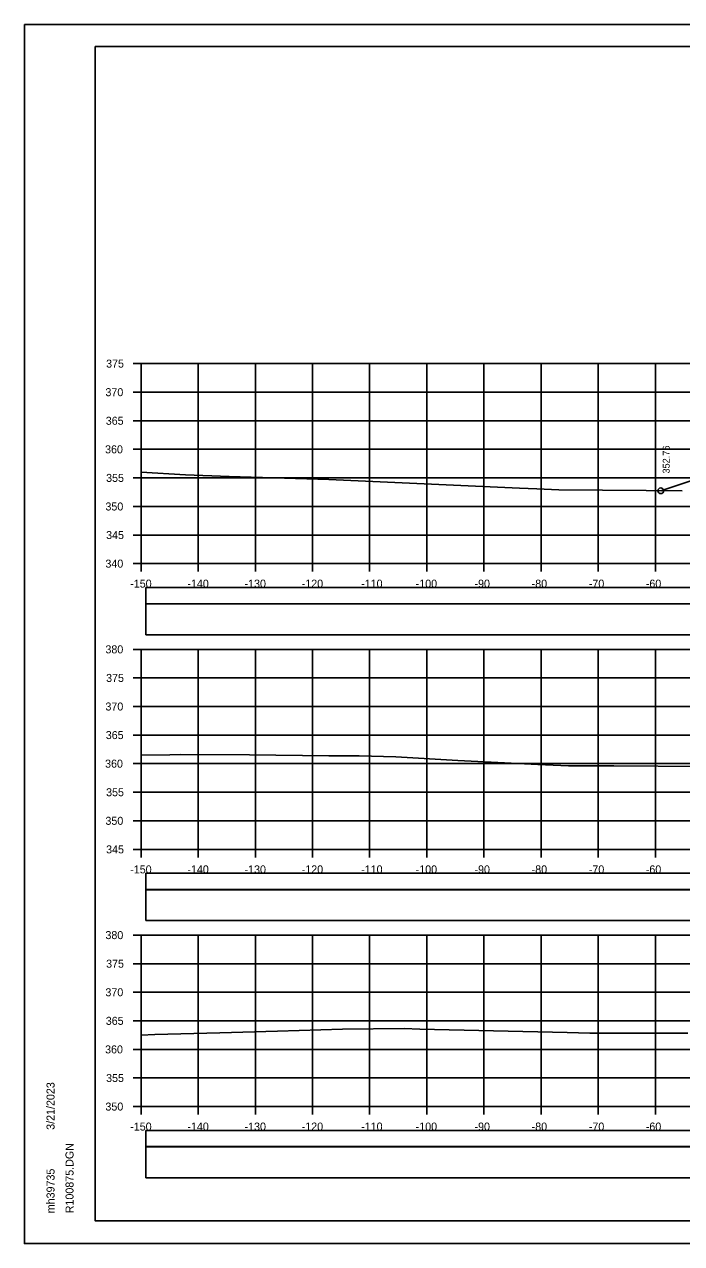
# Model space of a CAD drawing. Extents: x 1368122 to 1710785, y 373130 to 557566.
# Drawn here: x 1368518.5 to 1368633.5, y 376117.1 to 376330.4 of the extents above; entities that cross this region are included whole.
import ezdxf

# ---------------------------------------------------------------- set-up
doc = ezdxf.new("R2010")
doc.units = 0
for name, color, linetype in [('R_Alt Surface', 7, 'Continuous'), ('R_Axis', 7, 'Continuous'), ('R_Axis Annot', 7, 'Continuous'), ('R_Border', 7, 'Continuous'), ('R_Exist Surface', 7, 'Continuous'), ('R_Fin Surface', 7, 'Continuous'), ('R_Grid', 7, 'Continuous'), ('R_No Plot', 7, 'Continuous'), ('R_Xsect Elev', 7, 'Continuous')]:
    doc.layers.add(name, color=color, linetype=linetype)

msp = doc.modelspace()

# ---------------------------------------------------------------- linework, layer by layer
for points in [[(1368539.73, 376223.57), (1368838.03, 376223.57), (1368838.03, 376228.98), (1368539.73, 376228.98)], [(1368539.73, 376173.57), (1368838.03, 376173.57), (1368838.03, 376178.98), (1368539.73, 376178.98)], [(1368539.73, 376128.57), (1368838.03, 376128.57), (1368838.03, 376133.98), (1368539.73, 376133.98)]]:
    msp.add_lwpolyline(points, close=True)
at = {"layer": 'R_Alt Surface'}
for points in [[(1368539.73, 376229.03), (1368838.03, 376229.03), (1368838.03, 376231.85), (1368539.73, 376231.85)], [(1368539.73, 376179.03), (1368838.03, 376179.03), (1368838.03, 376181.85), (1368539.73, 376181.85)], [(1368539.73, 376134.03), (1368838.03, 376134.03), (1368838.03, 376136.85), (1368539.73, 376136.85)]]:
    msp.add_lwpolyline(points, close=True, dxfattribs=at)
at = {"layer": 'R_Axis'}
for p, q in [((1368537.48, 376271.04), (1368538.88, 376271.04)), ((1368538.88, 376236.04), (1368538.88, 376271.04)), ((1368537.48, 376266.04), (1368538.88, 376266.04)), ((1368537.48, 376261.04), (1368538.88, 376261.04)), ((1368537.48, 376256.04), (1368538.88, 376256.04)), ((1368537.48, 376251.04), (1368538.88, 376251.04)), ((1368537.48, 376246.04), (1368538.88, 376246.04)), ((1368537.48, 376241.04), (1368538.88, 376241.04)), ((1368537.48, 376236.04), (1368538.88, 376236.04)), ((1368538.88, 376236.04), (1368838.88, 376236.04)), ((1368538.88, 376234.64), (1368538.88, 376236.04)), ((1368548.88, 376234.64), (1368548.88, 376236.04)), ((1368558.88, 376234.64), (1368558.88, 376236.04)), ((1368568.88, 376234.64), (1368568.88, 376236.04)), ((1368578.88, 376234.64), (1368578.88, 376236.04)), ((1368588.88, 376234.64), (1368588.88, 376236.04)), ((1368598.88, 376234.64), (1368598.88, 376236.04)), ((1368608.88, 376234.64), (1368608.88, 376236.04)), ((1368618.88, 376234.64), (1368618.88, 376236.04)), ((1368628.88, 376234.64), (1368628.88, 376236.04)), ((1368537.48, 376221.04), (1368538.88, 376221.04)), ((1368538.88, 376186.04), (1368538.88, 376221.04)), ((1368537.48, 376216.04), (1368538.88, 376216.04)), ((1368537.48, 376211.04), (1368538.88, 376211.04)), ((1368537.48, 376206.04), (1368538.88, 376206.04)), ((1368537.48, 376201.04), (1368538.88, 376201.04)), ((1368537.48, 376196.04), (1368538.88, 376196.04)), ((1368537.48, 376191.04), (1368538.88, 376191.04)), ((1368537.48, 376186.04), (1368538.88, 376186.04)), ((1368538.88, 376186.04), (1368838.88, 376186.04)), ((1368538.88, 376184.64), (1368538.88, 376186.04)), ((1368548.88, 376184.64), (1368548.88, 376186.04)), ((1368558.88, 376184.64), (1368558.88, 376186.04)), ((1368568.88, 376184.64), (1368568.88, 376186.04)), ((1368578.88, 376184.64), (1368578.88, 376186.04)), ((1368588.88, 376184.64), (1368588.88, 376186.04)), ((1368598.88, 376184.64), (1368598.88, 376186.04)), ((1368608.88, 376184.64), (1368608.88, 376186.04)), ((1368618.88, 376184.64), (1368618.88, 376186.04)), ((1368628.88, 376184.64), (1368628.88, 376186.04)), ((1368537.48, 376171.04), (1368538.88, 376171.04)), ((1368538.88, 376141.04), (1368538.88, 376171.04)), ((1368537.48, 376166.04), (1368538.88, 376166.04)), ((1368537.48, 376161.04), (1368538.88, 376161.04)), ((1368537.48, 376156.04), (1368538.88, 376156.04)), ((1368537.48, 376151.04), (1368538.88, 376151.04)), ((1368537.48, 376146.04), (1368538.88, 376146.04)), ((1368537.48, 376141.04), (1368538.88, 376141.04)), ((1368538.88, 376141.04), (1368838.88, 376141.04)), ((1368538.88, 376139.64), (1368538.88, 376141.04)), ((1368548.88, 376139.64), (1368548.88, 376141.04)), ((1368558.88, 376139.64), (1368558.88, 376141.04)), ((1368568.88, 376139.64), (1368568.88, 376141.04)), ((1368578.88, 376139.64), (1368578.88, 376141.04)), ((1368588.88, 376139.64), (1368588.88, 376141.04)), ((1368598.88, 376139.64), (1368598.88, 376141.04)), ((1368608.88, 376139.64), (1368608.88, 376141.04)), ((1368618.88, 376139.64), (1368618.88, 376141.04)), ((1368628.88, 376139.64), (1368628.88, 376141.04))]:
    msp.add_line(p, q, dxfattribs=at)
at = {"layer": 'R_Border'}
for p, q in [((1368530.88, 376326.5), (1368847.06, 376326.5)), ((1368530.88, 376121.04), (1368530.88, 376326.5)), ((1368530.88, 376121.04), (1368530.88, 376121.04)), ((1368847.06, 376121.04), (1368530.88, 376121.04))]:
    msp.add_line(p, q, dxfattribs=at)
at = {"layer": 'R_Exist Surface'}
for points in [[(1368538.88, 376252.05), (1368546.66, 376251.59), (1368554.28, 376251.31), (1368571.75, 376250.78), (1368605.08, 376249.23), (1368608.12, 376249.11), (1368611.98, 376248.93), (1368627.25, 376248.83), (1368633.54, 376248.76)], [(1368538.88, 376202.51), (1368543.93, 376202.6), (1368545.82, 376202.64), (1368557.87, 376202.6), (1368571.76, 376202.42), (1368577.02, 376202.38), (1368583.45, 376202.24), (1368594.33, 376201.57), (1368608.3, 376200.89), (1368613.66, 376200.67), (1368621.62, 376200.68), (1368637.05, 376200.57)], [(1368538.88, 376153.52), (1368541.27, 376153.64), (1368552.66, 376153.96), (1368562.78, 376154.23), (1368574.1, 376154.57), (1368584.92, 376154.69), (1368587.67, 376154.61), (1368600.56, 376154.3), (1368613.45, 376153.97), (1368617.42, 376153.9), (1368634.56, 376153.86)]]:
    msp.add_lwpolyline(points, dxfattribs=at)
at = {"layer": 'R_Fin Surface'}
msp.add_lwpolyline([(1368629.81, 376248.8), (1368651.38, 376256), (1368656.38, 376255.9), (1368659.38, 376255.84), (1368659.88, 376255.84), (1368659.88, 376255.34), (1368660.88, 376255.36), (1368688.88, 376255.39), (1368716.88, 376254.83), (1368717.88, 376254.81), (1368717.88, 376255.31), (1368718.38, 376255.31), (1368721.38, 376255.37), (1368726.38, 376255.47), (1368727.96, 376254.95)], dxfattribs=at)
at = {"layer": 'R_Grid'}
for p, q in [((1368538.88, 376271.04), (1368838.88, 376271.04)), ((1368538.88, 376236.04), (1368538.88, 376271.04)), ((1368548.88, 376236.04), (1368548.88, 376271.04)), ((1368558.88, 376236.04), (1368558.88, 376271.04)), ((1368568.88, 376236.04), (1368568.88, 376271.04)), ((1368578.88, 376236.04), (1368578.88, 376271.04)), ((1368588.88, 376236.04), (1368588.88, 376271.04)), ((1368598.88, 376236.04), (1368598.88, 376271.04)), ((1368608.88, 376236.04), (1368608.88, 376271.04)), ((1368618.88, 376236.04), (1368618.88, 376271.04)), ((1368628.88, 376236.04), (1368628.88, 376271.04)), ((1368538.88, 376266.04), (1368838.88, 376266.04)), ((1368538.88, 376261.04), (1368838.88, 376261.04)), ((1368538.88, 376256.04), (1368838.88, 376256.04)), ((1368538.88, 376251.04), (1368838.88, 376251.04)), ((1368538.88, 376246.04), (1368838.88, 376246.04)), ((1368538.88, 376241.04), (1368838.88, 376241.04)), ((1368538.88, 376236.04), (1368838.88, 376236.04)), ((1368538.88, 376221.04), (1368838.88, 376221.04)), ((1368538.88, 376186.04), (1368538.88, 376221.04)), ((1368548.88, 376186.04), (1368548.88, 376221.04)), ((1368558.88, 376186.04), (1368558.88, 376221.04)), ((1368568.88, 376186.04), (1368568.88, 376221.04)), ((1368578.88, 376186.04), (1368578.88, 376221.04)), ((1368588.88, 376186.04), (1368588.88, 376221.04)), ((1368598.88, 376186.04), (1368598.88, 376221.04)), ((1368608.88, 376186.04), (1368608.88, 376221.04)), ((1368618.88, 376186.04), (1368618.88, 376221.04)), ((1368628.88, 376186.04), (1368628.88, 376221.04)), ((1368538.88, 376216.04), (1368838.88, 376216.04)), ((1368538.88, 376211.04), (1368838.88, 376211.04)), ((1368538.88, 376206.04), (1368838.88, 376206.04)), ((1368538.88, 376201.04), (1368838.88, 376201.04)), ((1368538.88, 376196.04), (1368838.88, 376196.04)), ((1368538.88, 376191.04), (1368838.88, 376191.04)), ((1368538.88, 376186.04), (1368838.88, 376186.04)), ((1368538.88, 376171.04), (1368838.88, 376171.04)), ((1368538.88, 376141.04), (1368538.88, 376171.04)), ((1368548.88, 376141.04), (1368548.88, 376171.04)), ((1368558.88, 376141.04), (1368558.88, 376171.04)), ((1368568.88, 376141.04), (1368568.88, 376171.04)), ((1368578.88, 376141.04), (1368578.88, 376171.04)), ((1368588.88, 376141.04), (1368588.88, 376171.04)), ((1368598.88, 376141.04), (1368598.88, 376171.04)), ((1368608.88, 376141.04), (1368608.88, 376171.04)), ((1368618.88, 376141.04), (1368618.88, 376171.04)), ((1368628.88, 376141.04), (1368628.88, 376171.04)), ((1368538.88, 376166.04), (1368838.88, 376166.04)), ((1368538.88, 376161.04), (1368838.88, 376161.04)), ((1368538.88, 376156.04), (1368838.88, 376156.04)), ((1368538.88, 376151.04), (1368838.88, 376151.04)), ((1368538.88, 376146.04), (1368838.88, 376146.04)), ((1368538.88, 376141.04), (1368838.88, 376141.04))]:
    msp.add_line(p, q, dxfattribs=at)
at = {"layer": 'R_No Plot'}
for p, q in [((1368518.48, 376330.4), (1368851.81, 376330.4)), ((1368518.48, 376117.06), (1368851.81, 376117.06))]:
    msp.add_line(p, q, dxfattribs=at)
for points in [[(1368518.47, 376330.4), (1368851.81, 376330.4), (1368851.81, 376117.06), (1368518.47, 376117.06)], [(1368764.8, 376326.5), (1368784.42, 376326.5), (1368784.42, 376316.62), (1368800.53, 376316.62), (1368823.73, 376316.62), (1368823.85, 376288.46), (1368847.06, 376288.46), (1368847.06, 376121.04), (1368530.88, 376121.04), (1368530.88, 376326.5)]]:
    msp.add_lwpolyline(points, close=True, dxfattribs=at)
msp.add_circle((1368629.81, 376248.8), 0.5, dxfattribs=at)

# ---------------------------------------------------------------- texts
at = {"layer": 'R_Axis Annot'}
for s, p in [('375', (1368532.77, 376270.34)), ('370', (1368532.65, 376265.34)), ('365', (1368532.71, 376260.34)), ('360', (1368532.59, 376255.34)), ('355', (1368532.77, 376250.34)), ('350', (1368532.65, 376245.34)), ('345', (1368532.77, 376240.34)), ('340', (1368532.65, 376235.34)), ('-150', (1368536.99, 376231.84)), ('-140', (1368546.99, 376231.84)), ('-130', (1368556.99, 376231.84)), ('-120', (1368566.99, 376231.84)), ('-110', (1368577.39, 376231.84)), ('-100', (1368586.93, 376231.84)), ('-90', (1368597.22, 376231.84)), ('-80', (1368607.22, 376231.84)), ('-70', (1368617.22, 376231.84)), ('-60', (1368627.19, 376231.84)), ('380', (1368532.65, 376220.34)), ('375', (1368532.77, 376215.34)), ('370', (1368532.65, 376210.34)), ('365', (1368532.71, 376205.34)), ('360', (1368532.59, 376200.34)), ('355', (1368532.77, 376195.34)), ('350', (1368532.65, 376190.34)), ('345', (1368532.77, 376185.34)), ('-150', (1368536.99, 376181.84)), ('-140', (1368546.99, 376181.84)), ('-130', (1368556.99, 376181.84)), ('-120', (1368566.99, 376181.84)), ('-110', (1368577.39, 376181.84)), ('-100', (1368586.93, 376181.84)), ('-90', (1368597.22, 376181.84)), ('-80', (1368607.22, 376181.84)), ('-70', (1368617.22, 376181.84)), ('-60', (1368627.19, 376181.84)), ('380', (1368532.65, 376170.34)), ('375', (1368532.77, 376165.34)), ('370', (1368532.65, 376160.34)), ('365', (1368532.71, 376155.34)), ('360', (1368532.59, 376150.34)), ('355', (1368532.77, 376145.34)), ('350', (1368532.65, 376140.34)), ('-150', (1368536.99, 376136.84)), ('-140', (1368546.99, 376136.84)), ('-130', (1368556.99, 376136.84)), ('-120', (1368566.99, 376136.84)), ('-110', (1368577.39, 376136.84)), ('-100', (1368586.93, 376136.84)), ('-90', (1368597.22, 376136.84)), ('-80', (1368607.22, 376136.84)), ('-70', (1368617.22, 376136.84)), ('-60', (1368627.19, 376136.84))]:
    msp.add_text(s, height=1.4, dxfattribs=at).set_placement(p)
at = {"layer": 'R_Border'}
for s, p in [('3/21/2023', (1368523.75, 376136.97)), ('R100875.DGN', (1368527.07, 376122.37)), ('mh39735', (1368523.75, 376122.37))]:
    msp.add_text(s, height=1.4, rotation=90, dxfattribs=at).set_placement(p)
at = {"layer": 'R_Xsect Elev'}
msp.add_text('352.76', height=1.2, rotation=90, dxfattribs=at).set_placement((1368631.36, 376251.8))

doc.saveas('drawing.dxf')
